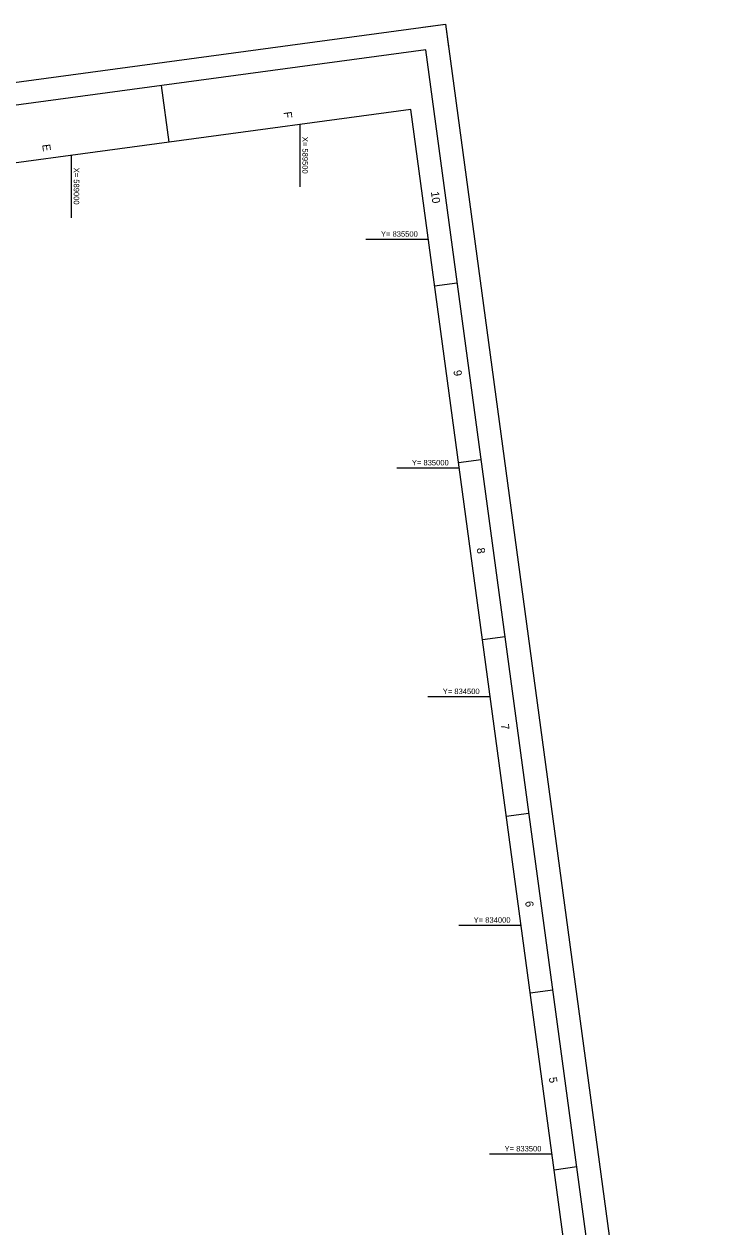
# Model space of a CAD drawing. Extents: x 586448 to 590407, y 831154 to 835970.
# Drawn here: x 588896 to 590407, y 833340 to 835970 of the extents above; entities that cross this region are included whole.
import ezdxf

# ---------------------------------------------------------------- set-up
doc = ezdxf.new("R2010")
doc.units = 0
for name, color, linetype in [('G-ANNO-NPLT', 7, 'Continuous'), ('G-ANNO-TTLB', 7, 'Continuous'), ('V-TOPO-COOR-STAT', 7, 'Continuous')]:
    doc.layers.add(name, color=color, linetype=linetype)

msp = doc.modelspace()

# ---------------------------------------------------------------- linework, layer by layer
at = {"layer": 'G-ANNO-NPLT'}
msp.add_lwpolyline([(589817.4, 835970.1), (590406.9, 831609.7), (587037.5, 831154.3), (586448.1, 835514.6)], close=True, dxfattribs=at)
msp.add_lwpolyline([(589767.9, 835963.4), (589817.4, 835970.1), (589824.1, 835920.5)], dxfattribs=at)
at = {"layer": 'G-ANNO-TTLB'}
for p, q in [((589196.3, 835835.6), (589213.1, 835711.8)), ((589843.6, 835403.5), (589794, 835396.8)), ((589895.8, 835017), (589846.3, 835010.3)), ((589895.8, 835017), (589846.3, 835010.3)), ((589948.1, 834630.5), (589898.5, 834623.8)), ((590000.3, 834244), (589950.7, 834237.3)), ((590052.5, 833857.5), (590003, 833850.8)), ((590104.8, 833471), (590055.2, 833464.3))]:
    msp.add_line(p, q, dxfattribs=at)
for points in [[(586504.3, 835471.7), (587080.4, 831210.5), (590350.6, 831652.6), (589774.6, 835913.8)], [(590294.4, 831695.4), (589741.8, 835783.2), (586570.6, 835354.5), (587123.2, 831266.8)]]:
    msp.add_lwpolyline(points, close=True, dxfattribs=at)
at = {"layer": 'V-TOPO-COOR-STAT'}
for p, q in [((589500, 835614.3), (589500, 835750.6)), ((589000, 835546.7), (589000, 835683)), ((589643.8, 835500), (589780.1, 835500)), ((589711.4, 835000), (589847.6, 835000)), ((589779, 834500), (589915.2, 834500)), ((589846.6, 834000), (589982.8, 834000)), ((589914.2, 833500), (590050.4, 833500))]:
    msp.add_line(p, q, dxfattribs=at)

# ---------------------------------------------------------------- texts
at = {"layer": 'G-ANNO-TTLB'}
for s, p in [('F', (589463.7, 835777.4)), ('E', (588935.8, 835706.2)), ('10', (589785.8, 835602.9)), ('9', (589835, 835212.2)), ('8', (589885.9, 834823.8)), ('7', (589938.7, 834438.7)), ('6', (589991.7, 834051.3)), ('5', (590043.7, 833666.4))]:
    msp.add_text(s, height=17.5, rotation=277.6988, dxfattribs=at).set_placement(p)
at = {"layer": 'V-TOPO-COOR-STAT'}
for s, p in [('X= 589500', (589504.8, 835723.5)), ('X= 589000', (589004.8, 835655.9))]:
    msp.add_text(s, height=12, rotation=270, dxfattribs=at).set_placement(p)
for s, p in [('Y= 835500', (589676.6, 835505)), ('Y= 835000', (589744.2, 835005)), ('Y= 834500', (589811.7, 834505)), ('Y= 834000', (589879.3, 834005)), ('Y= 833500', (589946.9, 833505))]:
    msp.add_text(s, height=12, dxfattribs=at).set_placement(p)

doc.saveas('drawing.dxf')
